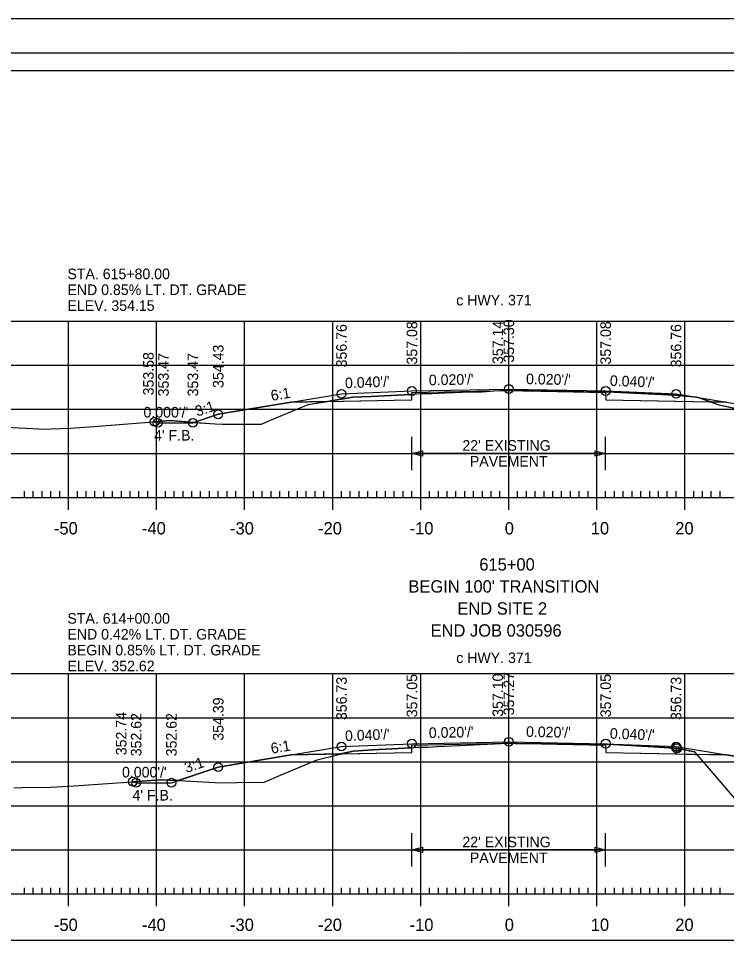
# Model space of a CAD drawing. Extents: x 1368910 to 1369601, y 380116 to 380950.
# Drawn here: x 1369381.9 to 1369462.3, y 380632.1 to 380737.1 of the extents above; entities that cross this region are included whole.
import ezdxf

# ---------------------------------------------------------------- set-up
doc = ezdxf.new("R2010")
doc.units = 0
for name, color, linetype in [('_STAGE 2 CUT', 7, 'Continuous'), ('_STAGE 2 FILL', 7, 'Continuous'), ('_STAGE 3 CUT', 7, 'Continuous'), ('_STAGE 3 FILL', 7, 'Continuous'), ('Notes', 7, 'Continuous'), ('R_Alt Surface', 7, 'Continuous'), ('R_Axis', 7, 'Continuous'), ('R_Axis Annot', 7, 'Continuous'), ('R_Border', 7, 'Continuous'), ('R_Exist Surface', 7, 'Continuous'), ('R_Fin Surface', 7, 'Continuous'), ('R_Grid', 7, 'Continuous'), ('R_No Plot', 7, 'Continuous'), ('R_ROW Annot', 7, 'Continuous'), ('R_Xsect Elev', 7, 'Continuous'), ('R_Xsect Slope', 7, 'Continuous')]:
    doc.layers.add(name, color=color, linetype=linetype)

msp = doc.modelspace()

# ---------------------------------------------------------------- linework, layer by layer
at = {"layer": '_STAGE 2 CUT'}
for p, q in [((1369448.59, 380694.76), (1369448.59, 380694.68)), ((1369459.1, 380694.11), (1369458.86, 380694.15)), ((1369460.53, 380693.6), (1369459.1, 380694.11)), ((1369448.59, 380654.75), (1369448.59, 380654.64)), ((1369456.59, 380653.65), (1369458.74, 380653.6)), ((1369458.74, 380653.6), (1369458.95, 380653.6))]:
    msp.add_line(p, q, dxfattribs=at)
for points in [[(1369458.86, 380694.15), (1369457.32, 380694.3), (1369457.06, 380694.33), (1369454.98, 380694.44), (1369448.76, 380694.76), (1369448.59, 380694.76)], [(1369448.59, 380694.68), (1369448.6, 380693.84), (1369450.59, 380693.8), (1369460.53, 380693.6)], [(1369458.95, 380653.6), (1369458.7, 380653.89), (1369458.31, 380653.98), (1369456.9, 380654.27), (1369456.59, 380654.29), (1369454.05, 380654.45), (1369448.79, 380654.74), (1369448.66, 380654.75), (1369448.59, 380654.75)], [(1369448.59, 380654.64), (1369448.6, 380653.81), (1369450.59, 380653.77), (1369456.59, 380653.65)], [(1369456.59, 380653.65), (1369456.59, 380653.65)], [(1369458.74, 380653.6), (1369458.74, 380653.6)]]:
    msp.add_lwpolyline(points, dxfattribs=at)
at = {"layer": '_STAGE 2 FILL'}
for p, q in [((1369462.32, 380693.57), (1369460.53, 380693.6)), ((1369462.32, 380653.53), (1369458.95, 380653.6))]:
    msp.add_line(p, q, dxfattribs=at)
for points in [[(1369437.59, 380694.9), (1369439.19, 380694.85), (1369439.58, 380694.85), (1369439.82, 380694.84), (1369440.13, 380694.85)], [(1369440.13, 380694.85), (1369439.82, 380694.85), (1369439.58, 380694.86), (1369437.59, 380694.9)], [(1369460.53, 380693.6), (1369461.34, 380693.32), (1369463.83, 380692.76), (1369467.16, 380692), (1369468.5, 380690.2), (1369469.74, 380689.52), (1369474.6, 380690.85)], [(1369437.59, 380654.86), (1369437.59, 380654.86)], [(1369437.59, 380654.86), (1369438.31, 380654.84), (1369438.55, 380654.84)], [(1369438.55, 380654.84), (1369438.31, 380654.85), (1369437.59, 380654.86)], [(1369458.95, 380653.6), (1369459.67, 380652.76), (1369463.23, 380648.59), (1369463.97, 380647.76), (1369467.33, 380644), (1369467.59, 380644.01), (1369473.12, 380644.16), (1369474.33, 380644.23), (1369477.42, 380647.33), (1369477.59, 380647.49)], [(1369481.34, 380648.57), (1369477.59, 380649.82), (1369470.59, 380652.15), (1369467.59, 380652.65), (1369466.96, 380652.76), (1369462.32, 380653.53)]]:
    msp.add_lwpolyline(points, dxfattribs=at)
at = {"layer": '_STAGE 3 CUT'}
for p, q in [((1369436.57, 380694.88), (1369437.29, 380694.89)), ((1369417.01, 380693.65), (1369424.59, 380693.8)), ((1369399.12, 380691.48), (1369397.37, 380691.34)), ((1369401.87, 380691.28), (1369399.12, 380691.48)), ((1369436.96, 380654.85), (1369437.35, 380654.86)), ((1369437.35, 380654.86), (1369437.52, 380654.86)), ((1369418.49, 380653.65), (1369424.59, 380653.77)), ((1369398.02, 380650.72), (1369394.89, 380650.5)), ((1369400.03, 380650.63), (1369398.02, 380650.72))]:
    msp.add_line(p, q, dxfattribs=at)
for points in [[(1369437.59, 380694.9), (1369437.45, 380694.9), (1369437.29, 380694.9), (1369436.57, 380694.88)], [(1369437.29, 380694.89), (1369437.45, 380694.89), (1369437.59, 380694.9)], [(1369426.59, 380694.46), (1369426.58, 380694.46), (1369426.47, 380694.45), (1369421.94, 380694.22), (1369419.88, 380694.12), (1369418.32, 380693.86), (1369417.01, 380693.65)], [(1369424.59, 380693.8), (1369426.58, 380693.84), (1369426.59, 380694.46)], [(1369397.37, 380691.34), (1369397.71, 380691.23), (1369401.71, 380691.23), (1369401.87, 380691.28)], [(1369437.52, 380654.86), (1369437.35, 380654.86), (1369436.96, 380654.85)], [(1369426.59, 380654.36), (1369426.47, 380654.35), (1369422.13, 380654.1), (1369419.92, 380653.96), (1369418.49, 380653.65)], [(1369424.59, 380653.77), (1369426.58, 380653.81), (1369426.59, 380654.36)], [(1369394.89, 380650.5), (1369395.27, 380650.38), (1369399.27, 380650.38), (1369400.03, 380650.63)]]:
    msp.add_lwpolyline(points, dxfattribs=at)
at = {"layer": '_STAGE 3 FILL'}
for p, q in [((1369417.01, 380693.65), (1369412.86, 380693.57)), ((1369418.49, 380653.65), (1369412.86, 380653.53))]:
    msp.add_line(p, q, dxfattribs=at)
for points in [[(1369401.87, 380691.28), (1369404.24, 380691.12), (1369405.06, 380691.06), (1369408.97, 380691.09), (1369409.52, 380691.09), (1369410.07, 380691.32), (1369414.8, 380693.29), (1369417.01, 380693.65)], [(1369412.86, 380693.57), (1369404.59, 380692.19), (1369401.87, 380691.28)], [(1369400.03, 380650.63), (1369400.17, 380650.63), (1369404.91, 380650.38), (1369406.75, 380650.39), (1369409.8, 380650.45), (1369411.94, 380651.35), (1369415.81, 380652.99), (1369418.44, 380653.63), (1369418.49, 380653.65)], [(1369412.86, 380653.53), (1369404.59, 380652.15), (1369400.03, 380650.63)]]:
    msp.add_lwpolyline(points, dxfattribs=at)
at = {"layer": 'R_Alt Surface'}
for points in [[(1369412.86, 380693.57), (1369424.59, 380693.8), (1369426.58, 380693.84), (1369426.59, 380694.68), (1369437.59, 380694.9), (1369448.59, 380694.68), (1369448.6, 380693.84), (1369450.59, 380693.8), (1369462.32, 380693.57)], [(1369412.86, 380653.53), (1369424.59, 380653.77), (1369426.58, 380653.81), (1369426.59, 380654.64), (1369437.59, 380654.86), (1369448.59, 380654.64), (1369448.6, 380653.81), (1369450.59, 380653.77), (1369462.32, 380653.53)], [(1369456.59, 380654.32), (1369456.59, 380653.65), (1369458.74, 380653.6)]]:
    msp.add_lwpolyline(points, dxfattribs=at)
at = {"layer": 'R_Axis'}
for p, q in [((1369387.59, 380681.36), (1369387.59, 380684.16)), ((1369397.59, 380681.36), (1369397.59, 380684.16)), ((1369407.59, 380681.36), (1369407.59, 380684.16)), ((1369417.59, 380681.36), (1369417.59, 380684.16)), ((1369427.59, 380681.36), (1369427.59, 380684.16)), ((1369437.59, 380681.36), (1369437.59, 380684.16)), ((1369447.59, 380681.36), (1369447.59, 380684.16)), ((1369457.59, 380681.36), (1369457.59, 380684.16)), ((1369382.59, 380682.76), (1369382.59, 380683.46)), ((1369383.59, 380682.76), (1369383.59, 380683.46)), ((1369384.59, 380682.76), (1369384.59, 380683.46)), ((1369385.59, 380682.76), (1369385.59, 380683.46)), ((1369386.59, 380682.76), (1369386.59, 380683.46)), ((1369388.59, 380682.76), (1369388.59, 380683.46)), ((1369389.59, 380682.76), (1369389.59, 380683.46)), ((1369390.59, 380682.76), (1369390.59, 380683.46)), ((1369391.59, 380682.76), (1369391.59, 380683.46)), ((1369392.59, 380682.76), (1369392.59, 380683.46)), ((1369393.59, 380682.76), (1369393.59, 380683.46)), ((1369394.59, 380682.76), (1369394.59, 380683.46)), ((1369395.59, 380682.76), (1369395.59, 380683.46)), ((1369396.59, 380682.76), (1369396.59, 380683.46)), ((1369398.59, 380682.76), (1369398.59, 380683.46)), ((1369399.59, 380682.76), (1369399.59, 380683.46)), ((1369400.59, 380682.76), (1369400.59, 380683.46)), ((1369401.59, 380682.76), (1369401.59, 380683.46)), ((1369402.59, 380682.76), (1369402.59, 380683.46)), ((1369403.59, 380682.76), (1369403.59, 380683.46)), ((1369404.59, 380682.76), (1369404.59, 380683.46)), ((1369405.59, 380682.76), (1369405.59, 380683.46)), ((1369406.59, 380682.76), (1369406.59, 380683.46)), ((1369408.59, 380682.76), (1369408.59, 380683.46)), ((1369409.59, 380682.76), (1369409.59, 380683.46)), ((1369410.59, 380682.76), (1369410.59, 380683.46)), ((1369411.59, 380682.76), (1369411.59, 380683.46)), ((1369412.59, 380682.76), (1369412.59, 380683.46)), ((1369413.59, 380682.76), (1369413.59, 380683.46)), ((1369414.59, 380682.76), (1369414.59, 380683.46)), ((1369415.59, 380682.76), (1369415.59, 380683.46)), ((1369416.59, 380682.76), (1369416.59, 380683.46)), ((1369418.59, 380682.76), (1369418.59, 380683.46)), ((1369419.59, 380682.76), (1369419.59, 380683.46)), ((1369420.59, 380682.76), (1369420.59, 380683.46)), ((1369421.59, 380682.76), (1369421.59, 380683.46)), ((1369422.59, 380682.76), (1369422.59, 380683.46)), ((1369423.59, 380682.76), (1369423.59, 380683.46)), ((1369424.59, 380682.76), (1369424.59, 380683.46)), ((1369425.59, 380682.76), (1369425.59, 380683.46)), ((1369426.59, 380682.76), (1369426.59, 380683.46)), ((1369428.59, 380682.76), (1369428.59, 380683.46)), ((1369429.59, 380682.76), (1369429.59, 380683.46)), ((1369430.59, 380682.76), (1369430.59, 380683.46)), ((1369431.59, 380682.76), (1369431.59, 380683.46)), ((1369432.59, 380682.76), (1369432.59, 380683.46)), ((1369433.59, 380682.76), (1369433.59, 380683.46)), ((1369434.59, 380682.76), (1369434.59, 380683.46)), ((1369435.59, 380682.76), (1369435.59, 380683.46)), ((1369436.59, 380682.76), (1369436.59, 380683.46)), ((1369438.59, 380682.76), (1369438.59, 380683.46)), ((1369439.59, 380682.76), (1369439.59, 380683.46)), ((1369440.59, 380682.76), (1369440.59, 380683.46)), ((1369441.59, 380682.76), (1369441.59, 380683.46)), ((1369442.59, 380682.76), (1369442.59, 380683.46)), ((1369443.59, 380682.76), (1369443.59, 380683.46)), ((1369444.59, 380682.76), (1369444.59, 380683.46)), ((1369445.59, 380682.76), (1369445.59, 380683.46)), ((1369446.59, 380682.76), (1369446.59, 380683.46)), ((1369448.59, 380682.76), (1369448.59, 380683.46)), ((1369449.59, 380682.76), (1369449.59, 380683.46)), ((1369450.59, 380682.76), (1369450.59, 380683.46)), ((1369451.59, 380682.76), (1369451.59, 380683.46)), ((1369452.59, 380682.76), (1369452.59, 380683.46)), ((1369453.59, 380682.76), (1369453.59, 380683.46)), ((1369454.59, 380682.76), (1369454.59, 380683.46)), ((1369455.59, 380682.76), (1369455.59, 380683.46)), ((1369456.59, 380682.76), (1369456.59, 380683.46)), ((1369458.59, 380682.76), (1369458.59, 380683.46)), ((1369459.59, 380682.76), (1369459.59, 380683.46)), ((1369460.59, 380682.76), (1369460.59, 380683.46)), ((1369461.59, 380682.76), (1369461.59, 380683.46)), ((1369297.59, 380682.76), (1369577.59, 380682.76)), ((1369387.59, 380636.36), (1369387.59, 380639.16)), ((1369397.59, 380636.36), (1369397.59, 380639.16)), ((1369407.59, 380636.36), (1369407.59, 380639.16)), ((1369417.59, 380636.36), (1369417.59, 380639.16)), ((1369427.59, 380636.36), (1369427.59, 380639.16)), ((1369437.59, 380636.36), (1369437.59, 380639.16)), ((1369447.59, 380636.36), (1369447.59, 380639.16)), ((1369457.59, 380636.36), (1369457.59, 380639.16)), ((1369382.59, 380637.76), (1369382.59, 380638.46)), ((1369383.59, 380637.76), (1369383.59, 380638.46)), ((1369384.59, 380637.76), (1369384.59, 380638.46)), ((1369385.59, 380637.76), (1369385.59, 380638.46)), ((1369386.59, 380637.76), (1369386.59, 380638.46)), ((1369388.59, 380637.76), (1369388.59, 380638.46)), ((1369389.59, 380637.76), (1369389.59, 380638.46)), ((1369390.59, 380637.76), (1369390.59, 380638.46)), ((1369391.59, 380637.76), (1369391.59, 380638.46)), ((1369392.59, 380637.76), (1369392.59, 380638.46)), ((1369393.59, 380637.76), (1369393.59, 380638.46)), ((1369394.59, 380637.76), (1369394.59, 380638.46)), ((1369395.59, 380637.76), (1369395.59, 380638.46)), ((1369396.59, 380637.76), (1369396.59, 380638.46)), ((1369398.59, 380637.76), (1369398.59, 380638.46)), ((1369399.59, 380637.76), (1369399.59, 380638.46)), ((1369400.59, 380637.76), (1369400.59, 380638.46)), ((1369401.59, 380637.76), (1369401.59, 380638.46)), ((1369402.59, 380637.76), (1369402.59, 380638.46)), ((1369403.59, 380637.76), (1369403.59, 380638.46)), ((1369404.59, 380637.76), (1369404.59, 380638.46)), ((1369405.59, 380637.76), (1369405.59, 380638.46)), ((1369406.59, 380637.76), (1369406.59, 380638.46)), ((1369408.59, 380637.76), (1369408.59, 380638.46)), ((1369409.59, 380637.76), (1369409.59, 380638.46)), ((1369410.59, 380637.76), (1369410.59, 380638.46)), ((1369411.59, 380637.76), (1369411.59, 380638.46)), ((1369412.59, 380637.76), (1369412.59, 380638.46)), ((1369413.59, 380637.76), (1369413.59, 380638.46)), ((1369414.59, 380637.76), (1369414.59, 380638.46)), ((1369415.59, 380637.76), (1369415.59, 380638.46)), ((1369416.59, 380637.76), (1369416.59, 380638.46)), ((1369418.59, 380637.76), (1369418.59, 380638.46)), ((1369419.59, 380637.76), (1369419.59, 380638.46)), ((1369420.59, 380637.76), (1369420.59, 380638.46)), ((1369421.59, 380637.76), (1369421.59, 380638.46)), ((1369422.59, 380637.76), (1369422.59, 380638.46)), ((1369423.59, 380637.76), (1369423.59, 380638.46)), ((1369424.59, 380637.76), (1369424.59, 380638.46)), ((1369425.59, 380637.76), (1369425.59, 380638.46)), ((1369426.59, 380637.76), (1369426.59, 380638.46)), ((1369428.59, 380637.76), (1369428.59, 380638.46)), ((1369429.59, 380637.76), (1369429.59, 380638.46)), ((1369430.59, 380637.76), (1369430.59, 380638.46)), ((1369431.59, 380637.76), (1369431.59, 380638.46)), ((1369432.59, 380637.76), (1369432.59, 380638.46)), ((1369433.59, 380637.76), (1369433.59, 380638.46)), ((1369434.59, 380637.76), (1369434.59, 380638.46)), ((1369435.59, 380637.76), (1369435.59, 380638.46)), ((1369436.59, 380637.76), (1369436.59, 380638.46)), ((1369438.59, 380637.76), (1369438.59, 380638.46)), ((1369439.59, 380637.76), (1369439.59, 380638.46)), ((1369440.59, 380637.76), (1369440.59, 380638.46)), ((1369441.59, 380637.76), (1369441.59, 380638.46)), ((1369442.59, 380637.76), (1369442.59, 380638.46)), ((1369443.59, 380637.76), (1369443.59, 380638.46)), ((1369444.59, 380637.76), (1369444.59, 380638.46)), ((1369445.59, 380637.76), (1369445.59, 380638.46)), ((1369446.59, 380637.76), (1369446.59, 380638.46)), ((1369448.59, 380637.76), (1369448.59, 380638.46)), ((1369449.59, 380637.76), (1369449.59, 380638.46)), ((1369450.59, 380637.76), (1369450.59, 380638.46)), ((1369451.59, 380637.76), (1369451.59, 380638.46)), ((1369452.59, 380637.76), (1369452.59, 380638.46)), ((1369453.59, 380637.76), (1369453.59, 380638.46)), ((1369454.59, 380637.76), (1369454.59, 380638.46)), ((1369455.59, 380637.76), (1369455.59, 380638.46)), ((1369456.59, 380637.76), (1369456.59, 380638.46)), ((1369458.59, 380637.76), (1369458.59, 380638.46)), ((1369459.59, 380637.76), (1369459.59, 380638.46)), ((1369460.59, 380637.76), (1369460.59, 380638.46)), ((1369461.59, 380637.76), (1369461.59, 380638.46)), ((1369297.59, 380637.76), (1369577.59, 380637.76))]:
    msp.add_line(p, q, dxfattribs=at)
at = {"layer": 'R_Border'}
for p, q in [((1369279.59, 380733.22), (1369595.77, 380733.22)), ((1369432.11, 380732.96), (1369432.11, 380732.96)), ((1369432.11, 380732.96), (1369432.11, 380732.96))]:
    msp.add_line(p, q, dxfattribs=at)
at = {"layer": 'R_Exist Surface'}
for points in [[(1369380.52, 380690.74), (1369384.96, 380690.5), (1369385.59, 380690.53), (1369387.8, 380690.62), (1369390.46, 380690.82), (1369399.12, 380691.48), (1369404.24, 380691.12), (1369405.06, 380691.06), (1369408.97, 380691.09), (1369409.52, 380691.09), (1369410.07, 380691.32), (1369414.8, 380693.29), (1369418.32, 380693.86), (1369419.88, 380694.12), (1369421.94, 380694.22), (1369426.47, 380694.45), (1369426.58, 380694.46), (1369427.77, 380694.54), (1369428.47, 380694.54), (1369428.86, 380694.55), (1369431.12, 380694.67), (1369431.44, 380694.68), (1369432.3, 380694.69), (1369433.52, 380694.75), (1369434.56, 380694.76), (1369435.04, 380694.78), (1369435.9, 380694.85), (1369437.29, 380694.9), (1369437.45, 380694.9), (1369439.19, 380694.85), (1369439.58, 380694.85), (1369439.82, 380694.84), (1369443.64, 380694.86), (1369443.85, 380694.87), (1369445.76, 380694.8), (1369446.1, 380694.79), (1369448.45, 380694.76), (1369448.76, 380694.76), (1369454.98, 380694.44), (1369457.06, 380694.33), (1369457.32, 380694.3), (1369459.03, 380694.13), (1369461.34, 380693.32), (1369467.16, 380692)], [(1369381.39, 380649.8), (1369382.36, 380649.82), (1369385.53, 380649.86), (1369388.24, 380650.03), (1369398.02, 380650.72), (1369400.17, 380650.63), (1369404.91, 380650.38), (1369406.75, 380650.39), (1369409.8, 380650.45), (1369411.94, 380651.35), (1369415.81, 380652.99), (1369418.44, 380653.63), (1369419.92, 380653.96), (1369422.13, 380654.1), (1369426.47, 380654.35), (1369426.72, 380654.36), (1369427.23, 380654.4), (1369427.77, 380654.42), (1369428.42, 380654.43), (1369429.49, 380654.5), (1369432, 380654.62), (1369435.95, 380654.81), (1369437.35, 380654.86), (1369438.31, 380654.84), (1369439.71, 380654.83), (1369440.46, 380654.84), (1369441.95, 380654.86), (1369443.87, 380654.84), (1369444.71, 380654.81), (1369445.36, 380654.81), (1369447.71, 380654.77), (1369448.55, 380654.76), (1369448.66, 380654.75), (1369448.79, 380654.74), (1369454.05, 380654.45), (1369456.9, 380654.27), (1369458.31, 380653.98), (1369458.7, 380653.89), (1369463.23, 380648.59)]]:
    msp.add_lwpolyline(points, dxfattribs=at)
at = {"layer": 'R_Fin Surface'}
for points in [[(1369397.37, 380691.34), (1369397.71, 380691.23), (1369401.71, 380691.23), (1369404.59, 380692.19), (1369412.86, 380693.57), (1369418.59, 380694.52), (1369426.59, 380694.84), (1369437.59, 380695.06), (1369448.59, 380694.84), (1369456.59, 380694.52), (1369462.32, 380693.57), (1369470.59, 380692.19), (1369479.51, 380689.22), (1369487.15, 380689.22), (1369494.66, 380691.72)], [(1369394.89, 380650.5), (1369395.27, 380650.38), (1369399.27, 380650.38), (1369404.59, 380652.15), (1369412.86, 380653.53), (1369418.59, 380654.49), (1369426.59, 380654.81), (1369437.59, 380655.03), (1369448.59, 380654.81), (1369456.59, 380654.49), (1369462.32, 380653.53), (1369470.59, 380652.15), (1369488.38, 380646.22), (1369496.38, 380646.22), (1369508.59, 380650.29)]]:
    msp.add_lwpolyline(points, dxfattribs=at)
at = {"layer": 'R_Grid'}
for p, q in [((1369297.59, 380702.76), (1369577.59, 380702.76)), ((1369387.59, 380682.76), (1369387.59, 380702.76)), ((1369397.59, 380682.76), (1369397.59, 380702.76)), ((1369407.59, 380682.76), (1369407.59, 380702.76)), ((1369417.59, 380682.76), (1369417.59, 380702.76)), ((1369427.59, 380682.76), (1369427.59, 380702.76)), ((1369437.59, 380682.76), (1369437.59, 380702.76)), ((1369447.59, 380682.76), (1369447.59, 380702.76)), ((1369457.59, 380682.76), (1369457.59, 380702.76)), ((1369297.59, 380697.76), (1369577.59, 380697.76)), ((1369297.59, 380692.76), (1369577.59, 380692.76)), ((1369297.59, 380687.76), (1369577.59, 380687.76)), ((1369297.59, 380682.76), (1369577.59, 380682.76)), ((1369297.59, 380662.76), (1369577.59, 380662.76)), ((1369387.59, 380637.76), (1369387.59, 380662.76)), ((1369397.59, 380637.76), (1369397.59, 380662.76)), ((1369407.59, 380637.76), (1369407.59, 380662.76)), ((1369417.59, 380637.76), (1369417.59, 380662.76)), ((1369427.59, 380637.76), (1369427.59, 380662.76)), ((1369437.59, 380637.76), (1369437.59, 380662.76)), ((1369447.59, 380637.76), (1369447.59, 380662.76)), ((1369457.59, 380637.76), (1369457.59, 380662.76)), ((1369297.59, 380657.76), (1369577.59, 380657.76)), ((1369297.59, 380652.76), (1369577.59, 380652.76)), ((1369297.59, 380647.76), (1369577.59, 380647.76)), ((1369297.59, 380642.76), (1369577.59, 380642.76)), ((1369297.59, 380637.76), (1369577.59, 380637.76))]:
    msp.add_line(p, q, dxfattribs=at)
at = {"layer": 'R_No Plot'}
for points in [[(1369267.18, 380737.11), (1369600.52, 380737.11), (1369600.52, 380523.78), (1369267.18, 380523.78)], [(1369593.77, 380632.49), (1369281.59, 380632.49), (1369281.59, 380731.22), (1369531.13, 380731.22), (1369531.13, 380721.34), (1369548.67, 380721.34), (1369572.77, 380721.34), (1369572.77, 380699.01), (1369593.77, 380699.01)], [(1369281.59, 380731.22), (1369531.13, 380731.22), (1369531.13, 380721.34), (1369548.67, 380721.34), (1369572.77, 380721.34), (1369572.77, 380699.01), (1369593.77, 380699.01), (1369593.77, 380529.76), (1369281.59, 380529.76)]]:
    msp.add_lwpolyline(points, close=True, dxfattribs=at)
for centre in [(1369418.59, 380694.52), (1369426.59, 380694.84), (1369437.59, 380695.06), (1369448.59, 380694.84), (1369456.59, 380694.52), (1369404.59, 380692.19), (1369397.37, 380691.34), (1369397.71, 380691.23), (1369401.71, 380691.23), (1369418.59, 380654.49), (1369426.59, 380654.81), (1369437.59, 380655.03), (1369448.59, 380654.81), (1369456.59, 380654.49), (1369456.59, 380654.32), (1369456.69, 380654.29), (1369404.59, 380652.15), (1369394.89, 380650.5), (1369395.27, 380650.38), (1369399.27, 380650.38)]:
    msp.add_circle(centre, 0.5, dxfattribs=at)
at = {"layer": 'R_ROW Annot'}
for p, q in [((1369426.59, 380685.87), (1369426.59, 380689.64)), ((1369448.59, 380685.87), (1369448.59, 380689.64)), ((1369448.59, 380687.76), (1369426.59, 380687.76)), ((1369426.59, 380640.87), (1369426.59, 380644.64)), ((1369448.59, 380640.87), (1369448.59, 380644.64)), ((1369448.59, 380642.76), (1369426.59, 380642.76))]:
    msp.add_line(p, q, dxfattribs=at)
for points in [[(1369427.79, 380687.46), (1369426.59, 380687.76), (1369427.79, 380688.06)], [(1369447.39, 380688.06), (1369448.59, 380687.76), (1369447.39, 380687.46)], [(1369427.79, 380642.46), (1369426.59, 380642.76), (1369427.79, 380643.06)], [(1369447.39, 380643.06), (1369448.59, 380642.76), (1369447.39, 380642.46)]]:
    msp.add_lwpolyline(points, close=True, dxfattribs=at)

# ---------------------------------------------------------------- texts
at = {"layer": 'Notes'}
for s, p in [('STA. 615+80.00', (1369387.46, 380707.53)), ('END 0.85% LT. DT. GRADE', (1369387.46, 380705.73)), ('ELEV. 354.15', (1369387.46, 380703.93)), ('c HWY. 371', (1369431.62, 380704.55)), ('STA. 614+00.00', (1369387.46, 380668.43)), ('END 0.42% LT. DT. GRADE', (1369387.46, 380666.63)), ('BEGIN 0.85% LT. DT. GRADE', (1369387.46, 380664.83)), ('c HWY. 371', (1369431.62, 380663.96)), ('ELEV. 352.62', (1369387.46, 380663.03))]:
    msp.add_text(s, height=1.2, dxfattribs=at).set_placement(p)
at = {"layer": 'R_Axis Annot'}
for s, p in [('-50', (1369385.93, 380678.56)), ('-40', (1369395.93, 380678.56)), ('-30', (1369405.93, 380678.56)), ('-20', (1369415.93, 380678.56)), ('-10', (1369426.33, 380678.56)), ('0', (1369437.13, 380678.56)), ('10', (1369446.9, 380678.56)), ('20', (1369456.5, 380678.56)), ('615+00', (1369434.24, 380674.46)), ("BEGIN 100' TRANSITION", (1369426.19, 380671.96)), ('END SITE 2', (1369431.75, 380669.46)), ('END JOB 030596', (1369428.71, 380666.96)), ('-50', (1369385.93, 380633.56)), ('-40', (1369395.93, 380633.56)), ('-30', (1369405.93, 380633.56)), ('-20', (1369415.93, 380633.56)), ('-10', (1369426.33, 380633.56)), ('0', (1369437.13, 380633.56)), ('10', (1369446.9, 380633.56)), ('20', (1369456.5, 380633.56))]:
    msp.add_text(s, height=1.4, dxfattribs=at).set_placement(p)
at = {"layer": 'R_ROW Annot'}
for s, p in [("22' EXISTING", (1369432.32, 380688.06)), ('PAVEMENT', (1369433.17, 380686.26)), ("22' EXISTING", (1369432.32, 380643.06)), ('PAVEMENT', (1369433.17, 380641.26))]:
    msp.add_text(s, height=1.2, dxfattribs=at).set_placement(p)
at = {"layer": 'R_Xsect Elev'}
for s, p in [('356.76', (1369419.19, 380697.52)), ('357.08', (1369427.19, 380697.84)), ('357.14', (1369436.94, 380697.9)), ('357.30', (1369438.19, 380698.06)), ('357.08', (1369449.19, 380697.84)), ('356.76', (1369457.19, 380697.52)), ('354.43', (1369405.19, 380695.19)), ('353.58', (1369397.26, 380694.34)), ('353.47', (1369398.97, 380694.23)), ('353.47', (1369402.31, 380694.23)), ('356.73', (1369419.19, 380657.49)), ('357.05', (1369427.19, 380657.81)), ('357.10', (1369436.94, 380657.86)), ('357.27', (1369438.19, 380658.03)), ('357.05', (1369449.19, 380657.81)), ('356.73', (1369457.19, 380657.49)), ('354.39', (1369405.19, 380655.15)), ('352.74', (1369394.17, 380653.5)), ('352.62', (1369395.87, 380653.38)), ('352.62', (1369399.87, 380653.38))]:
    msp.add_text(s, height=1.2, rotation=90, dxfattribs=at).set_placement(p)
at = {"layer": 'R_Xsect Slope'}
for s, rotation, p in [("0.020'/'", 1.1458, (1369428.52, 380695.48)), ("0.020'/'", 358.8542, (1369439.54, 380695.62)), ("0.040'/'", 2.2906, (1369419.01, 380695.14)), ("0.040'/'", 357.7094, (1369449.05, 380695.43)), ('6:1', 9.4623, (1369410.66, 380693.71)), ('3:1', 18.4349, (1369402.2, 380691.92)), ("0.000'/'", 360, (1369396.1, 380691.83)), ("4' F.B.", 360, (1369397.3, 380689.21)), ("4' F.B.", 360, (1369397.3, 380689.21)), ("0.020'/'", 1.1458, (1369428.52, 380655.45)), ("0.020'/'", 358.8542, (1369439.54, 380655.59)), ("0.040'/'", 2.2906, (1369419.01, 380655.1)), ("0.040'/'", 357.7094, (1369449.05, 380655.39)), ('6:1', 9.4623, (1369410.66, 380653.67)), ('3:1', 18.4349, (1369400.98, 380651.48)), ("0.000'/'", 360, (1369393.66, 380650.98)), ("4' F.B.", 360, (1369394.85, 380648.36)), ("4' F.B.", 360, (1369394.85, 380648.36))]:
    msp.add_text(s, height=1.2, rotation=rotation, dxfattribs=at).set_placement(p)

doc.saveas('drawing.dxf')
